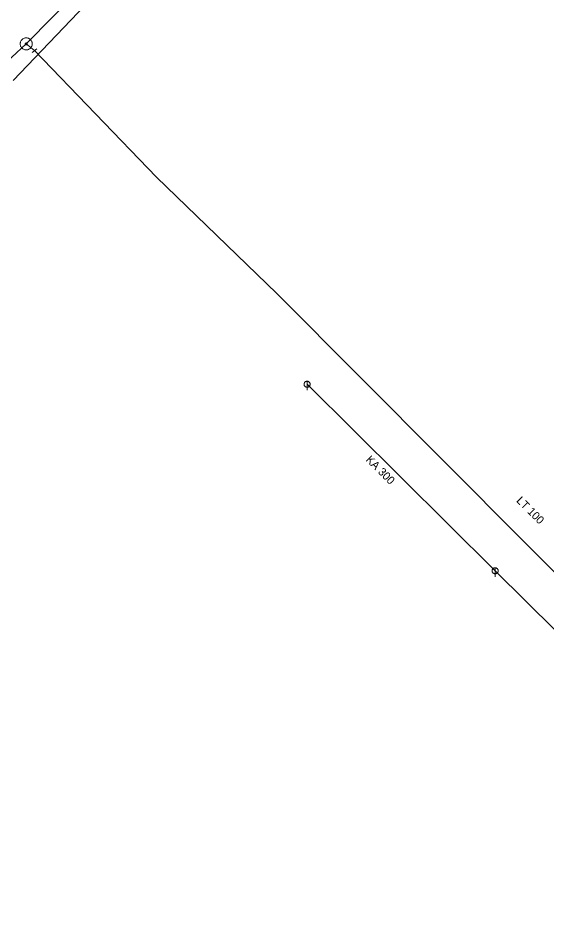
# Model space of a CAD drawing. Extents: x -687515 to -686506, y -974029 to -973461.
# Drawn here: x -687210.1 to -687166.1, y -973833.2 to -973757.5 of the extents above; entities that cross this region are included whole.
import ezdxf
from ezdxf.enums import TextEntityAlignment as Align

# ---------------------------------------------------------------- set-up
doc = ezdxf.new("R2010")
doc.units = 0
doc.header["$LTSCALE"] = 0.27
for name, color, linetype, lineweight in [('1', 7, 'Continuous', 13), ('14', 7, 'Continuous', 25), ('17', 7, 'Continuous', 25), ('22', 7, 'Continuous', 13), ('34', 7, 'Continuous', 13), ('47', 7, 'Continuous', 13)]:
    doc.layers.add(name, color=color, linetype=linetype, lineweight=lineweight)

msp = doc.modelspace()

# ---------------------------------------------------------------- linework, layer by layer
at = {"layer": '14'}
msp.add_line((-687210.551, -973762.688), (-687167.552, -973717.772), dxfattribs=at)
at = {"layer": '14', "lineweight": 13}
msp.add_line((-687208.769, -973760.209), (-687209.456, -973759.651), dxfattribs=at)
at = {"layer": '14'}
msp.add_lwpolyline([(-687186.05, -973787.989), (-687170.379, -973803.52), (-687155.19, -973818.55)], dxfattribs=at)
at = {"layer": '17'}
msp.add_line((-687209.456, -973759.651), (-687215.094, -973764.848), dxfattribs=at)
for points in [[(-687209.456, -973759.651), (-687158.031, -973707.595), (-687145.032, -973692.468)], [(-687112.499, -973830.523), (-687125.387, -973833.14), (-687131.526, -973833.246), (-687138.067, -973830.845), (-687146.977, -973822.133), (-687188.57, -973780.435), (-687198.6, -973770.76), (-687208.769, -973760.209)]]:
    msp.add_lwpolyline(points, dxfattribs=at)
at = {"layer": '22'}
for p, q in [((-687186.049, -973787.737), (-687186.05, -973788.48)), ((-687170.378, -973803.268), (-687170.379, -973804.012))]:
    msp.add_line(p, q, dxfattribs=at)
for points in [[(-687185.798, -973787.989), (-687185.799, -973787.963), (-687185.803, -973787.937), (-687185.809, -973787.911), (-687185.819, -973787.887), (-687185.831, -973787.863), (-687185.845, -973787.841), (-687185.862, -973787.82), (-687185.88, -973787.802), (-687185.901, -973787.785), (-687185.923, -973787.771), (-687185.947, -973787.759), (-687185.971, -973787.749), (-687185.997, -973787.743), (-687186.023, -973787.739), (-687186.049, -973787.737), (-687186.075, -973787.738), (-687186.101, -973787.742), (-687186.127, -973787.748), (-687186.152, -973787.758), (-687186.175, -973787.77), (-687186.197, -973787.784), (-687186.218, -973787.801), (-687186.236, -973787.819), (-687186.253, -973787.84), (-687186.267, -973787.862), (-687186.279, -973787.886), (-687186.289, -973787.91), (-687186.296, -973787.936), (-687186.3, -973787.962), (-687186.302, -973787.988), (-687186.301, -973788.014), (-687186.297, -973788.04), (-687186.29, -973788.066), (-687186.28, -973788.091), (-687186.268, -973788.114), (-687186.254, -973788.136), (-687186.237, -973788.157), (-687186.219, -973788.175), (-687186.198, -973788.192), (-687186.176, -973788.206), (-687186.153, -973788.218), (-687186.128, -973788.228), (-687186.102, -973788.235), (-687186.076, -973788.239), (-687186.05, -973788.24), (-687186.024, -973788.24), (-687185.998, -973788.236), (-687185.972, -973788.229), (-687185.948, -973788.219), (-687185.924, -973788.207), (-687185.902, -973788.193), (-687185.881, -973788.176), (-687185.863, -973788.158), (-687185.846, -973788.137), (-687185.832, -973788.115), (-687185.82, -973788.092), (-687185.81, -973788.067), (-687185.804, -973788.041), (-687185.8, -973788.015)], [(-687170.127, -973803.52), (-687170.128, -973803.494), (-687170.132, -973803.468), (-687170.138, -973803.442), (-687170.148, -973803.418), (-687170.16, -973803.394), (-687170.174, -973803.372), (-687170.191, -973803.351), (-687170.209, -973803.333), (-687170.23, -973803.316), (-687170.252, -973803.302), (-687170.276, -973803.29), (-687170.3, -973803.28), (-687170.326, -973803.274), (-687170.352, -973803.27), (-687170.378, -973803.268), (-687170.404, -973803.269), (-687170.43, -973803.273), (-687170.456, -973803.279), (-687170.481, -973803.289), (-687170.504, -973803.301), (-687170.526, -973803.315), (-687170.547, -973803.332), (-687170.565, -973803.35), (-687170.582, -973803.371), (-687170.596, -973803.393), (-687170.608, -973803.417), (-687170.618, -973803.441), (-687170.625, -973803.467), (-687170.629, -973803.493), (-687170.63, -973803.519), (-687170.63, -973803.545), (-687170.626, -973803.571), (-687170.619, -973803.597), (-687170.609, -973803.622), (-687170.597, -973803.645), (-687170.583, -973803.667), (-687170.566, -973803.688), (-687170.548, -973803.706), (-687170.527, -973803.723), (-687170.505, -973803.737), (-687170.482, -973803.749), (-687170.457, -973803.759), (-687170.431, -973803.766), (-687170.405, -973803.77), (-687170.379, -973803.772), (-687170.353, -973803.771), (-687170.327, -973803.767), (-687170.301, -973803.76), (-687170.277, -973803.75), (-687170.253, -973803.738), (-687170.231, -973803.724), (-687170.21, -973803.707), (-687170.192, -973803.689), (-687170.175, -973803.668), (-687170.161, -973803.646), (-687170.149, -973803.623), (-687170.139, -973803.598), (-687170.133, -973803.572), (-687170.129, -973803.546)]]:
    msp.add_lwpolyline(points, close=True, dxfattribs=at)
at = {"layer": '34'}
msp.add_line((-687208.964, -973760.361), (-687208.573, -973760.056), dxfattribs=at)
at = {"layer": '47'}
for points in [[(-687209.104, -973759.295), (-687209.143, -973759.261), (-687209.185, -973759.23), (-687209.231, -973759.205), (-687209.278, -973759.183), (-687209.328, -973759.167), (-687209.38, -973759.157), (-687209.432, -973759.152), (-687209.484, -973759.152), (-687209.536, -973759.157), (-687209.587, -973759.168), (-687209.637, -973759.185), (-687209.684, -973759.207), (-687209.73, -973759.232), (-687209.772, -973759.264), (-687209.811, -973759.299), (-687209.845, -973759.338), (-687209.876, -973759.38), (-687209.902, -973759.426), (-687209.923, -973759.473), (-687209.939, -973759.523), (-687209.949, -973759.575), (-687209.955, -973759.627), (-687209.955, -973759.68), (-687209.949, -973759.731), (-687209.938, -973759.782), (-687209.921, -973759.832), (-687209.9, -973759.88), (-687209.874, -973759.925), (-687209.842, -973759.967), (-687209.807, -973760.006), (-687209.768, -973760.04), (-687209.726, -973760.071), (-687209.68, -973760.098), (-687209.633, -973760.118), (-687209.583, -973760.134), (-687209.532, -973760.145), (-687209.479, -973760.151), (-687209.427, -973760.15), (-687209.375, -973760.144), (-687209.324, -973760.133), (-687209.274, -973760.116), (-687209.227, -973760.096), (-687209.181, -973760.069), (-687209.139, -973760.037), (-687209.1, -973760.002), (-687209.066, -973759.963), (-687209.035, -973759.921), (-687209.009, -973759.876), (-687208.988, -973759.828), (-687208.972, -973759.778), (-687208.961, -973759.727), (-687208.956, -973759.675), (-687208.956, -973759.623), (-687208.962, -973759.57), (-687208.973, -973759.519), (-687208.99, -973759.469), (-687209.011, -973759.422), (-687209.037, -973759.376), (-687209.069, -973759.334)], [(-687209.398, -973759.592), (-687209.404, -973759.586), (-687209.411, -973759.582), (-687209.418, -973759.577), (-687209.426, -973759.574), (-687209.435, -973759.571), (-687209.443, -973759.57), (-687209.452, -973759.568), (-687209.46, -973759.568), (-687209.469, -973759.57), (-687209.477, -973759.571), (-687209.486, -973759.574), (-687209.493, -973759.578), (-687209.5, -973759.582), (-687209.507, -973759.586), (-687209.514, -973759.593), (-687209.52, -973759.599), (-687209.524, -973759.606), (-687209.529, -973759.613), (-687209.532, -973759.621), (-687209.535, -973759.63), (-687209.536, -973759.638), (-687209.538, -973759.647), (-687209.538, -973759.655), (-687209.537, -973759.664), (-687209.535, -973759.672), (-687209.532, -973759.681), (-687209.528, -973759.688), (-687209.524, -973759.695), (-687209.52, -973759.702), (-687209.513, -973759.709), (-687209.507, -973759.715), (-687209.5, -973759.719), (-687209.493, -973759.724), (-687209.485, -973759.727), (-687209.476, -973759.73), (-687209.469, -973759.732), (-687209.459, -973759.733), (-687209.451, -973759.733), (-687209.442, -973759.732), (-687209.434, -973759.73), (-687209.425, -973759.727), (-687209.418, -973759.723), (-687209.411, -973759.719), (-687209.404, -973759.715), (-687209.397, -973759.708), (-687209.391, -973759.702), (-687209.387, -973759.695), (-687209.382, -973759.688), (-687209.379, -973759.68), (-687209.376, -973759.671), (-687209.374, -973759.664), (-687209.373, -973759.654), (-687209.373, -973759.646), (-687209.375, -973759.637), (-687209.376, -973759.629), (-687209.379, -973759.62), (-687209.383, -973759.613), (-687209.387, -973759.606), (-687209.391, -973759.599)]]:
    msp.add_lwpolyline(points, close=True, dxfattribs=at)

# ---------------------------------------------------------------- texts
at = {"layer": '1'}
for s, p in [('KA 300', (-687180.172, -973795.357)), ('LT 100', (-687167.674, -973798.714))]:
    msp.add_text(s, height=0.6667, rotation=315, dxfattribs=at).set_placement(p, align=Align.CENTER)

doc.saveas('drawing.dxf')
